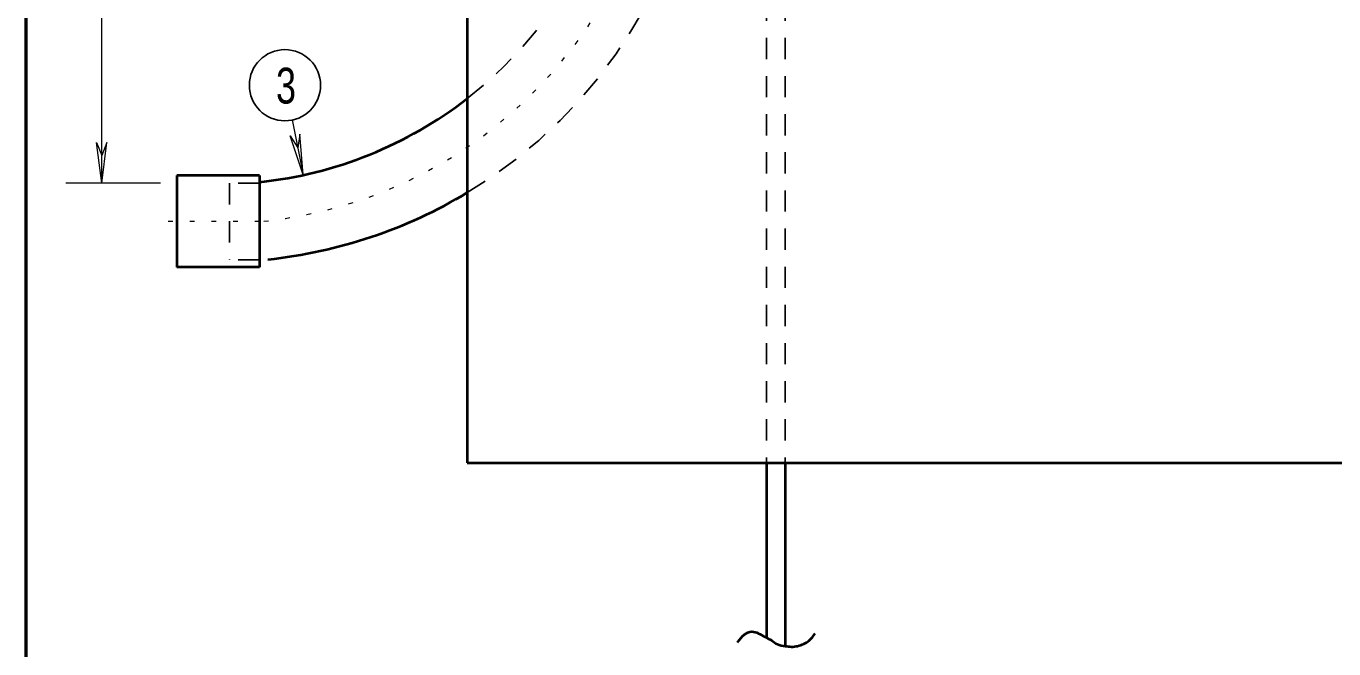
# Model space of a CAD drawing. Extents: x 312583 to 312854, y 144419 to 144597.
# Drawn here: x 312718.86 to 312746.6, y 144438.54 to 144451.76 of the extents above; entities that cross this region are included whole.
import ezdxf

# ---------------------------------------------------------------- set-up
doc = ezdxf.new("R2010")
doc.units = 0
doc.header["$LTSCALE"] = 0.3
doc.linetypes.add('DOTTED', pattern=[1.5, 0.3, -1.2])
doc.linetypes.add('SHORT_DASHED', pattern=[2.7, 1.5, -1.2])
doc.layers.add('1', color=7, linetype='Continuous', lineweight=25)
doc.layers.add('2', color=7, linetype='Continuous', lineweight=13)

msp = doc.modelspace()

# ---------------------------------------------------------------- linework, layer by layer
at = {"layer": '1', "lineweight": 53}
msp.add_line((312718.861, 144423.0846), (312718.861, 144506.4889), dxfattribs=at)
at = {"layer": '1', "lineweight": 40}
for p, q in [((312728.2202, 144464.8505), (312728.2202, 144442.4868)), ((312723.8119, 144448.5895), (312722.0562, 144448.5895)), ((312722.0562, 144448.5895), (312722.0562, 144446.6421)), ((312723.8119, 144448.5895), (312723.8119, 144446.6421)), ((312723.8119, 144446.6421), (312722.0562, 144446.6421)), ((312728.2202, 144442.4868), (312794.6672, 144442.4868)), ((312734.5682, 144442.4868), (312734.5682, 144438.7761)), ((312734.9669, 144442.4868), (312734.9669, 144438.5998))]:
    msp.add_line(p, q, dxfattribs=at)
at = {"layer": '1', "linetype": 'SHORT_DASHED'}
for p, q in [((312734.5682, 144457.1838), (312734.5682, 144442.4868)), ((312734.9669, 144457.1838), (312734.9669, 144442.4868)), ((312723.1756, 144448.4285), (312723.1756, 144446.8031)), ((312723.8119, 144448.4285), (312723.1756, 144448.4285)), ((312723.8119, 144446.8031), (312723.1756, 144446.8031))]:
    msp.add_line(p, q, dxfattribs=at)
at = {"layer": '1', "linetype": 'DOTTED', "lineweight": 13}
msp.add_line((312723.8119, 144447.6158), (312721.5119, 144447.6158), dxfattribs=at)
msp.add_arc((312722.8929, 144457.0978), 9.5322, 276.07999, 1.63993, dxfattribs=at)
at = {"layer": '1', "linetype": 'SHORT_DASHED'}
for radius, start, end in [(8.6946, 307.77967, 1.64033), (10.3468, 300.9843, 355.99394)]:
    msp.add_arc((312722.8929, 144457.0978), radius, start, end, dxfattribs=at)
at = {"layer": '1', "lineweight": 40}
for radius, end in [(8.6946, 307.78076), (10.3468, 300.98461)]:
    msp.add_arc((312722.8929, 144457.0978), radius, 276.07999, end, dxfattribs=at)
msp.add_spline([(312733.9549, 144438.6765), (312734.1006, 144438.8451), (312734.2539, 144438.9065), (312734.3996, 144438.8681), (312734.5376, 144438.7915), (312734.6832, 144438.7148), (312734.7982, 144438.6381), (312734.9669, 144438.5998), (312735.0972, 144438.5845), (312735.2276, 144438.5998), (312735.4729, 144438.7148), (312735.6032, 144438.8681)], degree=3, dxfattribs=at)
at = {"layer": '2'}
for p, q in [((312724.5019, 144449.7701), (312724.7396, 144448.6048)), ((312720.3568, 144449.2948), (312720.4642, 144449.0188)), ((312720.4642, 144448.4285), (312720.3568, 144449.2948)), ((312720.5715, 144449.2948), (312720.4642, 144449.0188)), ((312720.4642, 144448.4285), (312720.5715, 144449.2948)), ((312724.4636, 144449.4328), (312724.6246, 144449.1798)), ((312724.7396, 144448.6048), (312724.4636, 144449.4328)), ((312724.6706, 144449.4711), (312724.6246, 144449.1798)), ((312724.7396, 144448.6048), (312724.6706, 144449.4711)), ((312721.7112, 144448.4285), (312719.702, 144448.4285))]:
    msp.add_line(p, q, dxfattribs=at)
msp.add_lwpolyline([(312720.4642, 144448.4285), (312720.4642, 144463.5701), (312720.4642, 144465.4868)], dxfattribs=at)
at = {"layer": '2', "lineweight": 25}
msp.add_circle((312724.3518, 144450.5087), 0.7557, dxfattribs=at)

# ---------------------------------------------------------------- texts
at = {"layer": '2', "width": 0.75}
msp.add_text('3', height=0.76, dxfattribs=at).set_placement((312724.1619, 144450.1199))

doc.saveas('drawing.dxf')
